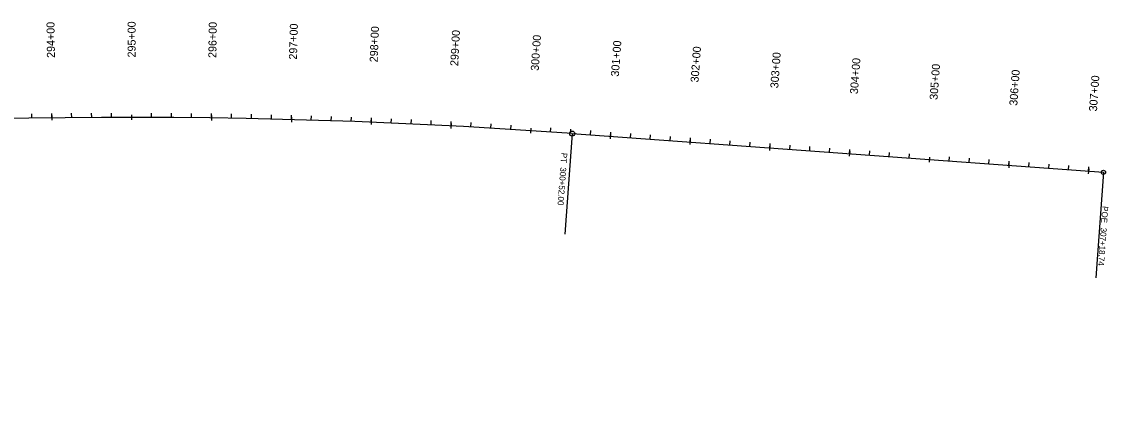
# Model space of a CAD drawing. Extents: x 20524607 to 20530050, y 8067105 to 8068411.
# Drawn here: x 20528690 to 20530050, y 8067836 to 8068313 of the extents above; entities that cross this region are included whole.
import ezdxf

# ---------------------------------------------------------------- set-up
doc = ezdxf.new("R2010")
doc.units = 0
for name, color, linetype in [('Contours Major', 7, 'Continuous'), ('Default', 7, 'Continuous'), ('Draft_DNC', 7, 'Continuous'), ('LiDAR', 7, 'Continuous'), ('Terrain', 7, 'Continuous')]:
    doc.layers.add(name, color=color, linetype=linetype)

msp = doc.modelspace()

# ---------------------------------------------------------------- linework, layer by layer
at = {"layer": 'Contours Major'}
for p, q in [((20528727.3, 8068192.4), (20528727.2, 8068197.9)), ((20528827.3, 8068196.1), (20528827.3, 8068190)), ((20528927.3, 8068192.3), (20528927.3, 8068197.8)), ((20529027.2, 8068190.3), (20529027.4, 8068195.8)), ((20529127.2, 8068187), (20529127.4, 8068192.5)), ((20529227.1, 8068182.4), (20529227.4, 8068187.8)), ((20529327.1, 8068179.5), (20529326.7, 8068173.4)), ((20529426.6, 8068169.4), (20529427, 8068174.8)), ((20529526.4, 8068162.1), (20529526.8, 8068167.5)), ((20529626.1, 8068154.8), (20529626.5, 8068160.3)), ((20529725.9, 8068147.5), (20529726.2, 8068153)), ((20529825.8, 8068143.3), (20529825.4, 8068137.2)), ((20529925.3, 8068133), (20529925.7, 8068138.4)), ((20530025.1, 8068125.7), (20530025.5, 8068131.2))]:
    msp.add_line(p, q, dxfattribs=at)
at = {"layer": 'Default'}
msp.add_line((20529378.8, 8068172.8), (20530043.7, 8068124.4), dxfattribs=at)
msp.add_arc((20528823.8, 8060560.6), 7632.4, 85.82989, 107.60125, dxfattribs=at)
at = {"layer": 'Draft_DNC'}
for p, q in [((20529378.8, 8068172.8), (20529369.6, 8068047.2)), ((20530043.7, 8068124.4), (20530034.1, 8067992.7)), ((20529369.6, 8068047.2), (20529369.6, 8068047.2)), ((20530034.1, 8067992.7), (20530034.1, 8067992.7))]:
    msp.add_line(p, q, dxfattribs=at)
for centre, radius in [((20529378.8, 8068172.8), 3.12), ((20530043.7, 8068124.4), 2.67)]:
    msp.add_circle(centre, radius, dxfattribs=at)
at = {"layer": 'LiDAR'}
for p, q in [((20528702.3, 8068192.1), (20528702.2, 8068197.5)), ((20528727.2, 8068195.5), (20528727.3, 8068189.4)), ((20528752.3, 8068192.7), (20528752.2, 8068198.2)), ((20528777.3, 8068192.9), (20528777.2, 8068198.4)), ((20528802.3, 8068193), (20528802.2, 8068198.5)), ((20528827.3, 8068196.1), (20528827.3, 8068190)), ((20528852.3, 8068193), (20528852.3, 8068198.5)), ((20528877.3, 8068192.9), (20528877.3, 8068198.3)), ((20528902.3, 8068192.6), (20528902.3, 8068198.1)), ((20528927.3, 8068195.4), (20528927.2, 8068189.3)), ((20528952.3, 8068192), (20528952.3, 8068197.4)), ((20528977.3, 8068191.5), (20528977.4, 8068197)), ((20529002.2, 8068191), (20529002.4, 8068196.4)), ((20529027.3, 8068193.4), (20529027.2, 8068187.3)), ((20529052.2, 8068189.6), (20529052.4, 8068195.1)), ((20529077.2, 8068188.8), (20529077.4, 8068194.3)), ((20529102.2, 8068188), (20529102.4, 8068193.4)), ((20529127.3, 8068190.1), (20529127.1, 8068184)), ((20529152.2, 8068186), (20529152.4, 8068191.4)), ((20529177.1, 8068184.9), (20529177.4, 8068190.3)), ((20529202.1, 8068183.7), (20529202.4, 8068189.1)), ((20529227.2, 8068185.4), (20529226.9, 8068179.3)), ((20529252, 8068181), (20529252.3, 8068186.5)), ((20529277, 8068179.6), (20529277.3, 8068185)), ((20529301.9, 8068178.1), (20529302.3, 8068183.5)), ((20529327.1, 8068179.5), (20529326.7, 8068173.4)), ((20529351.8, 8068174.8), (20529352.2, 8068180.2)), ((20529376.8, 8068173), (20529377.2, 8068178.4)), ((20529401.7, 8068171.2), (20529402.1, 8068176.6)), ((20529426.9, 8068172.4), (20529426.4, 8068166.3)), ((20529451.6, 8068167.5), (20529452, 8068173)), ((20529476.5, 8068165.7), (20529476.9, 8068171.2)), ((20529501.4, 8068163.9), (20529501.8, 8068169.3)), ((20529526.6, 8068165.1), (20529526.2, 8068159)), ((20529551.3, 8068160.3), (20529551.7, 8068165.7)), ((20529576.2, 8068158.4), (20529576.6, 8068163.9)), ((20529601.2, 8068156.6), (20529601.6, 8068162.1)), ((20529626.3, 8068157.9), (20529625.9, 8068151.8)), ((20529651.1, 8068153), (20529651.4, 8068158.4)), ((20529676, 8068151.2), (20529676.4, 8068156.6)), ((20529700.9, 8068149.4), (20529701.3, 8068154.8)), ((20529726.1, 8068150.6), (20529725.6, 8068144.5)), ((20529750.8, 8068145.7), (20529751.2, 8068151.2)), ((20529775.7, 8068143.9), (20529776.1, 8068149.3)), ((20529800.7, 8068142.1), (20529801.1, 8068147.5)), ((20529825.8, 8068143.3), (20529825.4, 8068137.2)), ((20529850.5, 8068138.4), (20529850.9, 8068143.9)), ((20529875.5, 8068136.6), (20529875.9, 8068142.1)), ((20529900.4, 8068134.8), (20529900.8, 8068140.3)), ((20529925.5, 8068136), (20529925.1, 8068129.9)), ((20529950.3, 8068131.2), (20529950.7, 8068136.6)), ((20529975.2, 8068129.4), (20529975.6, 8068134.8)), ((20530000.1, 8068127.5), (20530000.5, 8068133)), ((20530025.3, 8068128.8), (20530024.8, 8068122.7))]:
    msp.add_line(p, q, dxfattribs=at)
at = {"layer": 'Terrain'}
msp.add_line((20529378.8, 8068172.8), (20530043.7, 8068124.4), dxfattribs=at)
msp.add_arc((20528823.8, 8060560.6), 7632.4, 85.82989, 107.60125, dxfattribs=at)

# ---------------------------------------------------------------- texts
at = {"layer": 'Contours Major'}
for s, rotation, p in [('295+00', 89.9737, (20528832.3, 8068268)), ('300+00', 86.2202, (20529336.8, 8068251)), ('305+00', 85.8299, (20529836, 8068214.7))]:
    msp.add_text(s, height=10.02, rotation=rotation, dxfattribs=at).set_placement(p)
at = {"layer": 'Draft_DNC'}
for s, p in [('PT', (20529365.2, 8068149)), ('300+52.00', (20529363.9, 8068130.9)), ('POE ', (20530042.3, 8068082.4)), ('307+18.74', (20530040.4, 8068055.5))]:
    msp.add_text(s, height=7.5, rotation=265.8299, dxfattribs=at).set_placement(p)
at = {"layer": 'LiDAR'}
for s, rotation, p in [('294+00', 90.7244, (20528731.3, 8068267.5)), ('295+00', 89.9737, (20528832.3, 8068268)), ('296+00', 89.223, (20528933.3, 8068267.3)), ('297+00', 88.4723, (20529034.2, 8068265.2)), ('298+00', 87.7216, (20529135.2, 8068261.8)), ('299+00', 86.9709, (20529236, 8068257)), ('300+00', 86.2202, (20529336.8, 8068251)), ('301+00', 85.8299, (20529437.1, 8068243.8)), ('302+00', 85.8299, (20529536.8, 8068236.5)), ('303+00', 85.8299, (20529636.6, 8068229.2)), ('304+00', 85.8299, (20529736.3, 8068222)), ('305+00', 85.8299, (20529836, 8068214.7)), ('306+00', 85.8299, (20529935.8, 8068207.4)), ('307+00', 85.8299, (20530035.5, 8068200.2))]:
    msp.add_text(s, height=10.02, rotation=rotation, dxfattribs=at).set_placement(p)

doc.saveas('drawing.dxf')
